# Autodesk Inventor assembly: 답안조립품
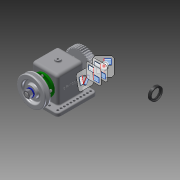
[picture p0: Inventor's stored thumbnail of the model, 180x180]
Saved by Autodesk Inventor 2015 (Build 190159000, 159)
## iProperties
Created: 2018-11
Part Number: 답안조립품
Document SubType Name: Assembly
Designer: now
Author: now
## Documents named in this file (13)
- C:\Users\now\Desktop\481108V1008\답안조립품.iam
- C:\Users\now\Desktop\481108V1008\V벨트풀리.ipt
- C:\Users\now\Desktop\481108V1008\너트 M12x1.25.ipt
- C:\Users\now\Desktop\481108V1008\베어링 6203.ipt
- C:\Users\now\Desktop\481108V1008\본체.ipt
- C:\Users\now\Desktop\481108V1008\볼트 M4.ipt
- C:\Users\now\Desktop\481108V1008\부시.ipt
- C:\Users\now\Desktop\481108V1008\스퍼기어.ipt
- C:\Users\now\Desktop\481108V1008\오일 실 26 38 8.ipt
- C:\Users\now\Desktop\481108V1008\와셔 12x24.ipt
- C:\Users\now\Desktop\481108V1008\축.ipt
- C:\Users\now\Desktop\481108V1008\커버.ipt
- C:\Users\now\Desktop\481108V1008\키 5x5x12.ipt
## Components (1 placed, 1 different names)
1. V벨트풀리:1 — 각도:3
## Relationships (1: Angle 1)
- 각도:3 [Angle]: V벨트풀리:1
